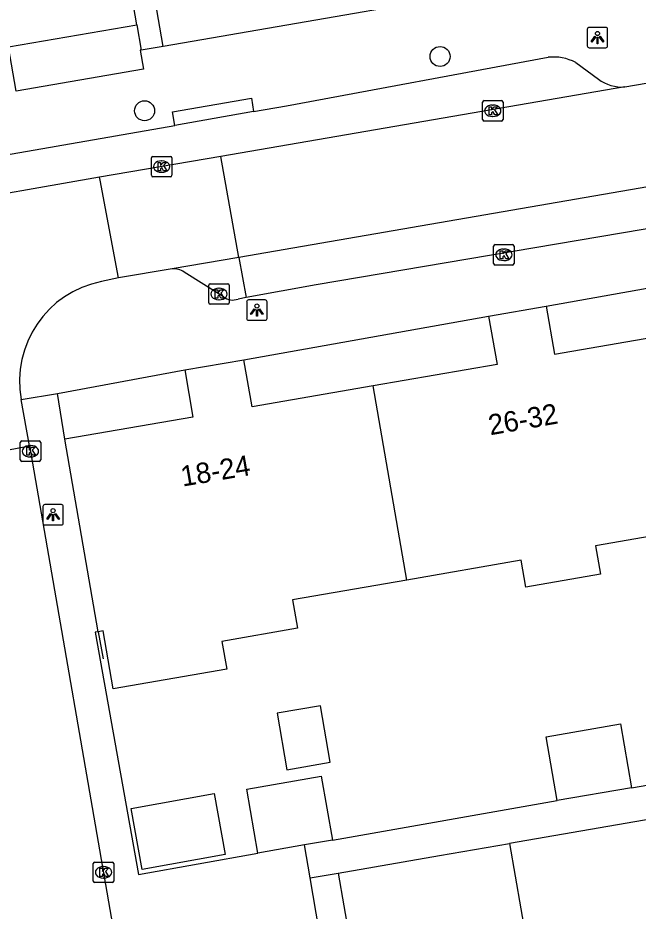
# Model space of a CAD drawing. Extents: x 162880 to 165536, y 384011 to 385179.
# Drawn here: x 164385.77 to 164416.13, y 384385.29 to 384429.02 of the extents above; entities that cross this region are included whole.
import ezdxf

# ---------------------------------------------------------------- set-up
doc = ezdxf.new("R2010")
doc.units = 0
for name, color, linetype in [('IMGEO_Boom', 7, 'Continuous'), ('IMGEO_Kolk', 7, 'Continuous'), ('IMGEO_Lichtpunt', 7, 'Continuous'), ('IMGEO_Muur', 7, 'Continuous'), ('IMGEO_Pand', 7, 'Continuous'), ('IMGEO_Pand_nummerreeks', 7, 'Continuous'), ('IMGEO_Parkeervlak_gesloten', 7, 'Continuous'), ('IMGEO_Rijbaan_lokaal_gesloten', 7, 'Continuous'), ('IMGEO_Rijbaan_lokaal_open', 7, 'Continuous'), ('IMGEO_Voetpad_open', 7, 'Continuous')]:
    doc.layers.add(name, color=color, linetype=linetype)

msp = doc.modelspace()

# ---------------------------------------------------------------- linework, layer by layer
at = {"layer": 'IMGEO_Boom'}
for centre in [(164406.433, 384427.126), (164391.973, 384424.47)]:
    msp.add_circle(centre, 0.489, dxfattribs=at)
at = {"layer": 'IMGEO_Kolk'}
for p, q in [((164408.513, 384424.043), (164408.513, 384424.895)), ((164408.588, 384424.969), (164409.44, 384424.969)), ((164409.514, 384424.895), (164409.514, 384424.043)), ((164409.001, 384424.749), (164409.026, 384424.749)), ((164409.44, 384423.969), (164408.588, 384423.969)), ((164409.024, 384424.189), (164408.999, 384424.189)), ((164392.385, 384422.237), (164393.237, 384422.237)), ((164392.31, 384421.311), (164392.31, 384422.163)), ((164392.798, 384422.017), (164392.823, 384422.017)), ((164393.311, 384422.163), (164393.311, 384421.311)), ((164392.821, 384421.457), (164392.796, 384421.457)), ((164393.237, 384421.237), (164392.385, 384421.237)), ((164409.055, 384416.993), (164409.055, 384417.845)), ((164409.13, 384417.919), (164409.982, 384417.919)), ((164410.056, 384417.845), (164410.056, 384416.993)), ((164409.543, 384417.699), (164409.568, 384417.699)), ((164409.566, 384417.139), (164409.541, 384417.139)), ((164409.982, 384416.919), (164409.13, 384416.919)), ((164395.114, 384415.073), (164395.114, 384415.925)), ((164395.189, 384415.999), (164396.041, 384415.999)), ((164395.602, 384415.779), (164395.627, 384415.779)), ((164396.115, 384415.925), (164396.115, 384415.073)), ((164396.041, 384414.999), (164395.189, 384414.999)), ((164395.625, 384415.219), (164395.6, 384415.219)), ((164385.888, 384407.379), (164385.888, 384408.231)), ((164385.963, 384408.305), (164386.815, 384408.305)), ((164386.889, 384408.231), (164386.889, 384407.379)), ((164386.376, 384408.085), (164386.401, 384408.085)), ((164386.399, 384407.525), (164386.374, 384407.525)), ((164386.815, 384407.305), (164385.963, 384407.305)), ((164389.539, 384387.69), (164390.391, 384387.69)), ((164389.464, 384386.764), (164389.464, 384387.616)), ((164389.952, 384387.47), (164389.977, 384387.47)), ((164390.465, 384387.616), (164390.465, 384386.764)), ((164389.975, 384386.91), (164389.95, 384386.91)), ((164390.391, 384386.69), (164389.539, 384386.69))]:
    msp.add_line(p, q, dxfattribs=at)
for points in [[(164408.513, 384424.043), (164408.513, 384424.895)], [(164408.588, 384424.969), (164409.44, 384424.969)], [(164409.514, 384424.895), (164409.514, 384424.043)], [(164408.834, 384424.669), (164408.957, 384424.669), (164408.957, 384424.518), (164409.087, 384424.669), (164409.251, 384424.669), (164409.105, 384424.518), (164409.258, 384424.269), (164409.106, 384424.269), (164409.021, 384424.433), (164408.957, 384424.366), (164408.957, 384424.269), (164408.834, 384424.269), (164408.834, 384424.669)], [(164409.44, 384423.969), (164408.588, 384423.969)], [(164392.385, 384422.237), (164393.237, 384422.237)], [(164392.31, 384421.311), (164392.31, 384422.163)], [(164392.631, 384421.937), (164392.754, 384421.937), (164392.754, 384421.786), (164392.884, 384421.937), (164393.048, 384421.937), (164392.902, 384421.786), (164393.055, 384421.537), (164392.903, 384421.537), (164392.818, 384421.701), (164392.754, 384421.634), (164392.754, 384421.537), (164392.631, 384421.537), (164392.631, 384421.937)], [(164393.311, 384422.163), (164393.311, 384421.311)], [(164393.237, 384421.237), (164392.385, 384421.237)], [(164409.055, 384416.993), (164409.055, 384417.845)], [(164409.13, 384417.919), (164409.982, 384417.919)], [(164410.056, 384417.845), (164410.056, 384416.993)], [(164409.376, 384417.619), (164409.499, 384417.619), (164409.499, 384417.468), (164409.629, 384417.619), (164409.793, 384417.619), (164409.647, 384417.468), (164409.8, 384417.219), (164409.648, 384417.219), (164409.563, 384417.383), (164409.499, 384417.316), (164409.499, 384417.219), (164409.376, 384417.219), (164409.376, 384417.619)], [(164409.982, 384416.919), (164409.13, 384416.919)], [(164395.114, 384415.073), (164395.114, 384415.925)], [(164395.189, 384415.999), (164396.041, 384415.999)], [(164395.435, 384415.699), (164395.558, 384415.699), (164395.558, 384415.548), (164395.688, 384415.699), (164395.852, 384415.699), (164395.706, 384415.548), (164395.859, 384415.299), (164395.707, 384415.299), (164395.622, 384415.463), (164395.558, 384415.396), (164395.558, 384415.299), (164395.435, 384415.299), (164395.435, 384415.699)], [(164396.115, 384415.925), (164396.115, 384415.073)], [(164396.041, 384414.999), (164395.189, 384414.999)], [(164385.888, 384407.379), (164385.888, 384408.231)], [(164385.963, 384408.305), (164386.815, 384408.305)], [(164386.889, 384408.231), (164386.889, 384407.379)], [(164386.209, 384408.005), (164386.332, 384408.005), (164386.332, 384407.854), (164386.462, 384408.005), (164386.626, 384408.005), (164386.48, 384407.854), (164386.633, 384407.605), (164386.481, 384407.605), (164386.396, 384407.769), (164386.332, 384407.702), (164386.332, 384407.605), (164386.209, 384407.605), (164386.209, 384408.005)], [(164386.815, 384407.305), (164385.963, 384407.305)], [(164389.539, 384387.69), (164390.391, 384387.69)], [(164389.464, 384386.764), (164389.464, 384387.616)], [(164389.785, 384387.39), (164389.908, 384387.39), (164389.908, 384387.239), (164390.038, 384387.39), (164390.202, 384387.39), (164390.056, 384387.239), (164390.209, 384386.99), (164390.057, 384386.99), (164389.972, 384387.154), (164389.908, 384387.087), (164389.908, 384386.99), (164389.785, 384386.99), (164389.785, 384387.39)], [(164390.465, 384387.616), (164390.465, 384386.764)], [(164390.391, 384386.69), (164389.539, 384386.69)]]:
    msp.add_lwpolyline(points, dxfattribs=at)
for centre, start, end in [((164408.59, 384424.893), 91.552, 178.448), ((164408.59, 384424.893), 91.552, 178.448), ((164409.438, 384424.893), 1.552, 88.448), ((164409.438, 384424.893), 1.552, 88.448), ((164408.59, 384424.045), 181.552, 268.448), ((164408.59, 384424.045), 181.552, 268.448), ((164409.438, 384424.045), 271.552, 358.448), ((164409.438, 384424.045), 271.552, 358.448), ((164392.387, 384422.161), 91.552, 178.448), ((164392.387, 384422.161), 91.552, 178.448), ((164393.235, 384422.161), 1.552, 88.448), ((164393.235, 384422.161), 1.552, 88.448), ((164392.387, 384421.313), 181.552, 268.448), ((164392.387, 384421.313), 181.552, 268.448), ((164393.235, 384421.313), 271.552, 358.448), ((164393.235, 384421.313), 271.552, 358.448), ((164409.132, 384417.843), 91.552, 178.448), ((164409.132, 384417.843), 91.552, 178.448), ((164409.98, 384417.843), 1.552, 88.448), ((164409.98, 384417.843), 1.552, 88.448), ((164409.132, 384416.995), 181.552, 268.448), ((164409.132, 384416.995), 181.552, 268.448), ((164409.98, 384416.995), 271.552, 358.448), ((164409.98, 384416.995), 271.552, 358.448), ((164395.191, 384415.923), 91.552, 178.448), ((164395.191, 384415.923), 91.552, 178.448), ((164396.039, 384415.923), 1.552, 88.448), ((164396.039, 384415.923), 1.552, 88.448), ((164395.191, 384415.075), 181.552, 268.448), ((164395.191, 384415.075), 181.552, 268.448), ((164396.039, 384415.075), 271.552, 358.448), ((164396.039, 384415.075), 271.552, 358.448), ((164385.965, 384408.229), 91.552, 178.448), ((164385.965, 384408.229), 91.552, 178.448), ((164386.813, 384408.229), 1.552, 88.448), ((164386.813, 384408.229), 1.552, 88.448), ((164385.965, 384407.381), 181.552, 268.448), ((164385.965, 384407.381), 181.552, 268.448), ((164386.813, 384407.381), 271.552, 358.448), ((164386.813, 384407.381), 271.552, 358.448), ((164389.541, 384387.614), 91.552, 178.448), ((164389.541, 384387.614), 91.552, 178.448), ((164390.389, 384387.614), 1.552, 88.448), ((164390.389, 384387.614), 1.552, 88.448), ((164389.541, 384386.766), 181.552, 268.448), ((164389.541, 384386.766), 181.552, 268.448), ((164390.389, 384386.766), 271.552, 358.448), ((164390.389, 384386.766), 271.552, 358.448)]:
    msp.add_arc(centre, 0.0765, start, end, dxfattribs=at)
for centre, major_axis, ratio, start_param, end_param in [((164409, 384424.469), (-0.387, 0.002), 0.722429, 4.712389, 7.853982), ((164409.025, 384424.469), (-0.39, 0.002), 0.717154, 1.570796, 4.712389), ((164392.797, 384421.737), (-0.387, 0.002), 0.722429, 4.712389, 7.853982), ((164392.822, 384421.737), (-0.39, 0.002), 0.717154, 1.570796, 4.712389), ((164409.542, 384417.419), (-0.387, 0.002), 0.722429, 4.712389, 7.853982), ((164409.567, 384417.419), (-0.39, 0.002), 0.717154, 1.570796, 4.712389), ((164395.601, 384415.499), (-0.387, 0.002), 0.722429, 4.712389, 7.853982), ((164395.626, 384415.499), (-0.39, 0.002), 0.717154, 1.570796, 4.712389), ((164386.375, 384407.805), (-0.387, 0.002), 0.722429, 4.712389, 7.853982), ((164386.4, 384407.805), (-0.39, 0.002), 0.717154, 1.570796, 4.712389), ((164389.951, 384387.19), (-0.387, 0.002), 0.722429, 4.712389, 7.853982), ((164389.976, 384387.19), (-0.39, 0.002), 0.717154, 1.570796, 4.712389)]:
    msp.add_ellipse(centre, major_axis=major_axis, ratio=ratio, start_param=start_param, end_param=end_param, dxfattribs=at)
at = {"layer": 'IMGEO_Lichtpunt'}
for p, q in [((164413.638, 384428.456), (164413.638, 384427.649)), ((164413.638, 384428.456), (164413.638, 384427.649)), ((164414.54, 384428.551), (164413.732, 384428.551)), ((164414.54, 384428.551), (164413.732, 384428.551)), ((164414.634, 384427.649), (164414.634, 384428.456)), ((164414.634, 384427.649), (164414.634, 384428.456)), ((164413.732, 384427.555), (164414.54, 384427.555)), ((164413.732, 384427.555), (164414.54, 384427.555)), ((164396.97, 384415.116), (164396.97, 384414.309)), ((164396.97, 384415.116), (164396.97, 384414.309)), ((164397.872, 384415.211), (164397.064, 384415.211)), ((164397.872, 384415.211), (164397.064, 384415.211)), ((164397.966, 384414.309), (164397.966, 384415.116)), ((164397.966, 384414.309), (164397.966, 384415.116)), ((164397.064, 384414.215), (164397.872, 384414.215)), ((164397.064, 384414.215), (164397.872, 384414.215)), ((164387.9, 384405.191), (164387.092, 384405.191)), ((164387.9, 384405.191), (164387.092, 384405.191)), ((164386.998, 384405.096), (164386.998, 384404.289)), ((164386.998, 384405.096), (164386.998, 384404.289)), ((164387.994, 384404.289), (164387.994, 384405.096)), ((164387.994, 384404.289), (164387.994, 384405.096)), ((164387.092, 384404.195), (164387.9, 384404.195)), ((164387.092, 384404.195), (164387.9, 384404.195))]:
    msp.add_line(p, q, dxfattribs=at)
for points in [[(164414.012, 384428.12), (164414.051, 384428.092), (164413.863, 384427.83), (164413.825, 384427.857), (164414.012, 384428.12)], [(164414.114, 384428.072), (164414.161, 384428.072), (164414.161, 384427.75), (164414.114, 384427.75), (164414.114, 384428.072)], [(164414.224, 384428.092), (164414.262, 384428.119), (164414.449, 384427.857), (164414.41, 384427.829), (164414.224, 384428.092)], [(164397.344, 384414.78), (164397.383, 384414.752), (164397.195, 384414.49), (164397.157, 384414.517), (164397.344, 384414.78)], [(164397.446, 384414.732), (164397.493, 384414.732), (164397.493, 384414.41), (164397.446, 384414.41), (164397.446, 384414.732)], [(164397.556, 384414.752), (164397.594, 384414.779), (164397.781, 384414.517), (164397.742, 384414.489), (164397.556, 384414.752)], [(164387.372, 384404.76), (164387.411, 384404.732), (164387.223, 384404.47), (164387.185, 384404.497), (164387.372, 384404.76)], [(164387.584, 384404.732), (164387.622, 384404.759), (164387.809, 384404.497), (164387.77, 384404.469), (164387.584, 384404.732)], [(164387.474, 384404.712), (164387.521, 384404.712), (164387.521, 384404.39), (164387.474, 384404.39), (164387.474, 384404.712)]]:
    msp.add_lwpolyline(points, dxfattribs=at)
for centre in [(164414.137, 384428.254), (164397.469, 384414.914), (164387.497, 384404.894)]:
    msp.add_circle(centre, 0.0994, dxfattribs=at)
for centre, start, end in [((164413.732, 384428.456), 90, 180), ((164413.732, 384428.456), 90, 180), ((164414.54, 384428.456), 0, 90), ((164414.54, 384428.456), 0, 90), ((164413.732, 384427.649), 180, 270), ((164413.732, 384427.649), 180, 270), ((164414.54, 384427.649), 270, 0), ((164414.54, 384427.649), 270, 360), ((164397.064, 384415.116), 90, 180), ((164397.064, 384415.116), 90, 180), ((164397.872, 384415.116), 0, 90), ((164397.872, 384415.116), 0, 90), ((164397.064, 384414.309), 180, 270), ((164397.064, 384414.309), 180, 270), ((164397.872, 384414.309), 270, 0), ((164397.872, 384414.309), 270, 360), ((164387.092, 384405.096), 90, 180), ((164387.092, 384405.096), 90, 180), ((164387.9, 384405.096), 0, 90), ((164387.9, 384405.096), 0, 90), ((164387.092, 384404.289), 180, 270), ((164387.092, 384404.289), 180, 270), ((164387.9, 384404.289), 270, 0), ((164387.9, 384404.289), 270, 360)]:
    msp.add_arc(centre, 0.0946, start, end, dxfattribs=at)
at = {"layer": 'IMGEO_Muur'}
msp.add_lwpolyline([(164389.706, 384398.968), (164389.954, 384397.641)], dxfattribs=at)
at = {"layer": 'IMGEO_Pand'}
for points in [[(164391.593, 384428.673), (164390.748, 384433.601), (164389.955, 384438.22)], [(164385.689, 384425.428), (164385.317, 384427.596), (164391.593, 384428.673)], [(164408.812, 384414.415), (164411.629, 384414.903)], [(164411.629, 384414.903), (164412.035, 384412.559), (164418.164, 384413.621)], [(164408.812, 384414.415), (164409.222, 384412.053), (164403.157, 384411.002)], [(164393.944, 384411.783), (164396.831, 384412.283)], [(164403.157, 384411.002), (164397.231, 384409.975), (164396.831, 384412.283)], [(164393.944, 384411.783), (164394.343, 384409.479), (164388.073, 384408.392)], [(164404.807, 384401.498), (164403.157, 384411.002)], [(164389.706, 384398.968), (164388.073, 384408.392)], [(164419.771, 384404.164), (164414.043, 384403.171), (164414.283, 384401.788), (164410.632, 384401.155), (164410.404, 384402.468), (164404.807, 384401.498)], [(164404.807, 384401.498), (164399.218, 384400.53), (164399.46, 384399.135), (164395.756, 384398.493), (164395.992, 384397.135), (164390.442, 384396.174), (164389.95, 384399.01), (164389.706, 384398.968)], [(164401.063, 384392.583), (164400.584, 384395.348), (164398.464, 384394.98), (164398.943, 384392.216), (164401.063, 384392.583)], [(164412.16, 384390.7), (164411.618, 384393.823), (164415.263, 384394.454), (164415.805, 384391.33)], [(164397.518, 384388.136), (164396.976, 384391.261), (164400.621, 384391.892), (164401.163, 384388.768)], [(164415.805, 384391.33), (164412.16, 384390.7)], [(164395.915, 384388.065), (164391.861, 384387.333), (164391.323, 384390.31), (164395.378, 384391.042), (164395.915, 384388.065)], [(164401.163, 384388.768), (164399.799, 384388.532)], [(164401.452, 384387.155), (164406.41, 384388.013), (164409.825, 384388.605)], [(164409.825, 384388.605), (164410.933, 384382.211)], [(164399.799, 384388.532), (164397.518, 384388.136)], [(164401.452, 384387.155), (164402.56, 384380.76)]]:
    msp.add_lwpolyline(points, dxfattribs=at)
at = {"layer": 'IMGEO_Parkeervlak_gesloten'}
msp.add_lwpolyline([(164396.592, 384417.292), (164396.947, 384415.325)], dxfattribs=at)
at = {"layer": 'IMGEO_Rijbaan_lokaal_gesloten'}
for points in [[(164415.478, 384425.634), (164416.523, 384425.814)], [(164415.478, 384425.634), (164403.282, 384423.54), (164395.7, 384422.234)], [(164396.592, 384417.292), (164395.7, 384422.234)], [(164417.428, 384418.836), (164417.081, 384420.833), (164396.592, 384417.292)]]:
    msp.add_lwpolyline(points, dxfattribs=at)
at = {"layer": 'IMGEO_Rijbaan_lokaal_open'}
for points in [[(164395.7, 384422.234), (164389.77, 384421.213)], [(164389.77, 384421.213), (164373.791, 384418.419)], [(164390.7, 384416.291), (164389.795, 384421.07), (164389.77, 384421.213)], [(164396.592, 384417.292), (164393.324, 384416.731)], [(164393.324, 384416.731), (164390.7, 384416.291)], [(164390.7, 384416.291), (164389.863, 384416.109)], [(164386.344, 384408.063), (164385.941, 384410.333)], [(164381.51, 384407.155), (164386.344, 384408.063)], [(164386.344, 384408.063), (164390.64, 384383.301)]]:
    msp.add_lwpolyline(points, dxfattribs=at)
msp.add_arc((164390.816, 384411.243), 4.959, 101.0752, 190.5705, dxfattribs=at)
at = {"layer": 'IMGEO_Voetpad_open'}
for points in [[(164392.891, 384427.624), (164389.359, 384448.051)], [(164412.939, 384431.091), (164392.891, 384427.624)], [(164391.593, 384428.673), (164391.807, 384427.437)], [(164392.891, 384427.624), (164391.807, 384427.437)], [(164391.807, 384427.437), (164391.761, 384427.429), (164391.923, 384426.51), (164385.689, 384425.428)], [(164397.308, 384424.429), (164398.925, 384424.711), (164411.718, 384427.088)], [(164413.074, 384426.834), (164414.182, 384426.017)], [(164393.455, 384423.757), (164393.344, 384424.417), (164397.198, 384425.084), (164397.308, 384424.429)], [(164397.308, 384424.429), (164393.455, 384423.757)], [(164364.163, 384418.859), (164366.928, 384419.133), (164393.455, 384423.757)], [(164417.428, 384418.836), (164400.372, 384415.943), (164396.947, 384415.325)], [(164395.835, 384415.36), (164393.907, 384416.576)], [(164411.629, 384414.903), (164417.753, 384415.994)], [(164396.947, 384415.325), (164396.55, 384415.253)], [(164396.831, 384412.283), (164408.812, 384414.415)], [(164387.71, 384410.636), (164393.944, 384411.783)], [(164385.941, 384410.333), (164387.71, 384410.636)], [(164388.073, 384408.392), (164387.71, 384410.636)], [(164415.805, 384391.33), (164421.814, 384392.371), (164419.771, 384404.164)], [(164389.706, 384398.968), (164389.55, 384398.945), (164391.675, 384387.078), (164397.518, 384388.136)], [(164401.163, 384388.768), (164412.16, 384390.7)], [(164422.536, 384388.205), (164422.098, 384390.731), (164409.825, 384388.605)], [(164400.073, 384386.92), (164399.799, 384388.532)], [(164400.073, 384386.92), (164401.452, 384387.155)], [(164405.399, 384355.616), (164400.073, 384386.92)]]:
    msp.add_lwpolyline(points, dxfattribs=at)
for centre, radius, start, end in [((164411.973, 384424.702), 2.399, 62.6824, 96.0987), ((164415.347, 384427.575), 1.945, 233.2116, 273.861), ((164393.394, 384415.821), 0.913, 55.8114, 94.4114), ((164396.285, 384415.928), 0.725, 231.567, 291.4107)]:
    msp.add_arc(centre, radius, start, end, dxfattribs=at)

# ---------------------------------------------------------------- texts
at = {"layer": 'IMGEO_Pand_nummerreeks'}
for s, rotation, p in [('26-32', 9.9128, (164408.891, 384408.582)), ('18-24', 9.6429, (164393.834, 384406.071))]:
    msp.add_text(s, height=1, rotation=rotation, dxfattribs=at).set_placement(p)

doc.saveas('drawing.dxf')
